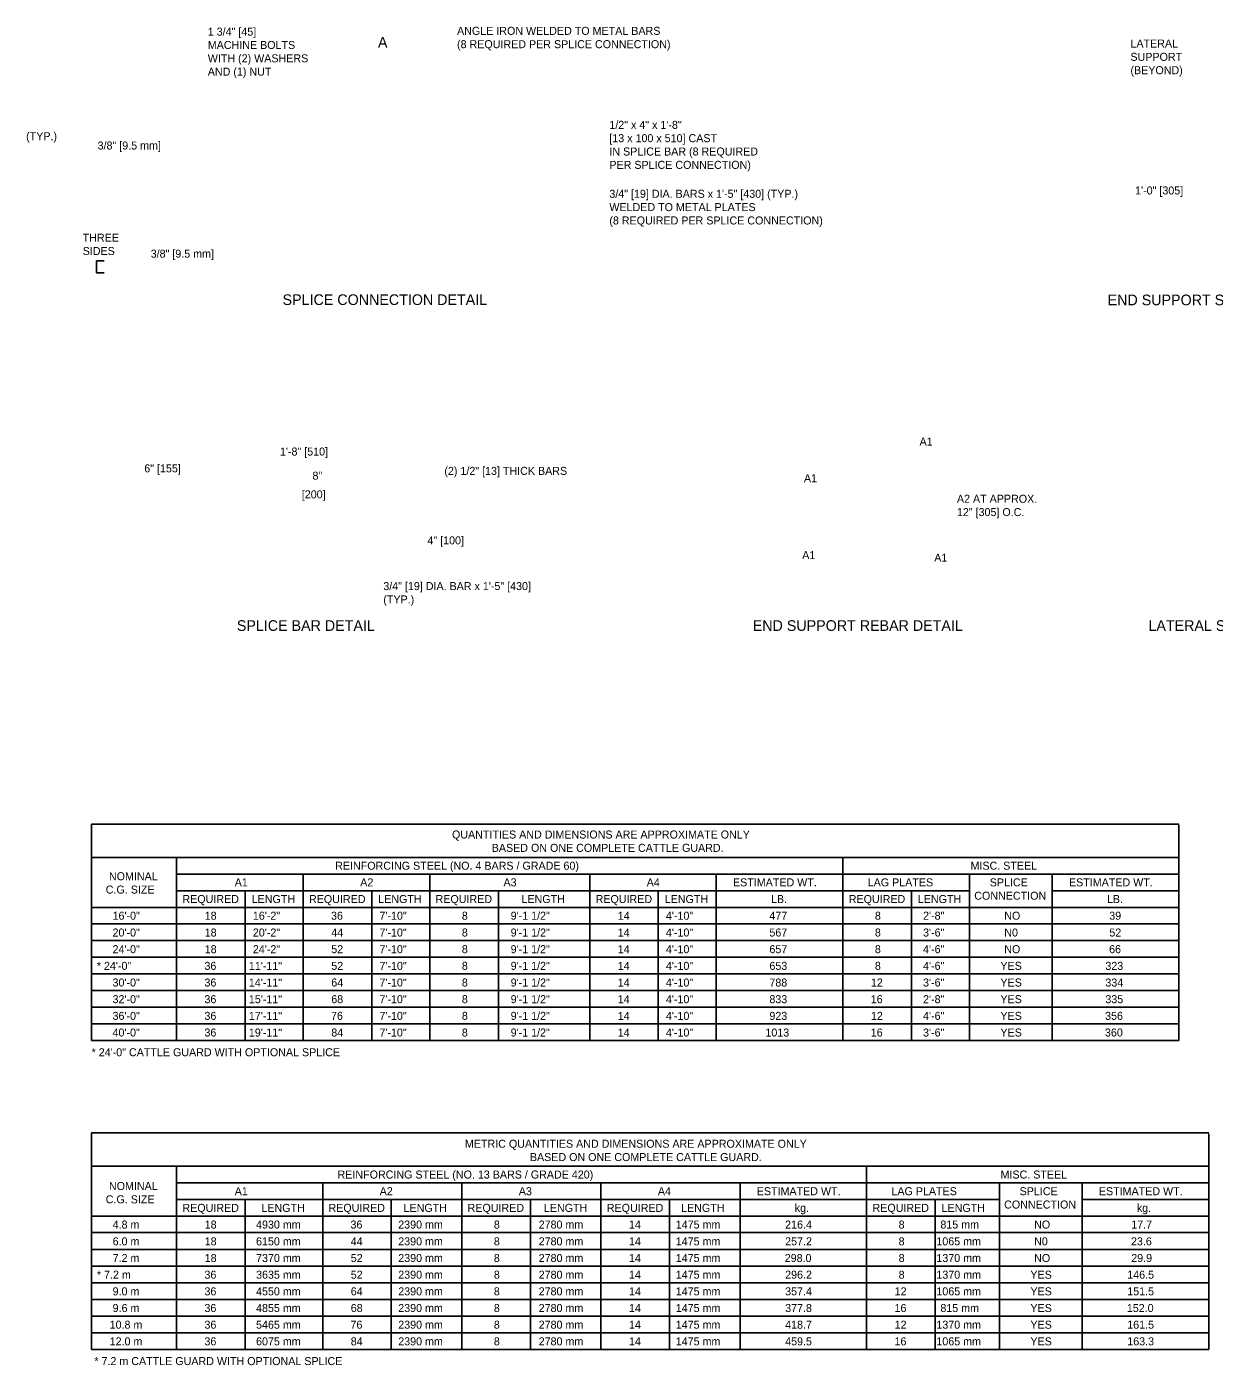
# Model space of a CAD drawing. Extents: x 49987.2 to 50044, y 49982.5 to 50011.4.
# Drawn here: x 50026.9 to 50035.8, y 49988.47 to 49998.51 of the extents above; entities that cross this region are included whole.
import ezdxf

# ---------------------------------------------------------------- set-up
doc = ezdxf.new("R2010")
doc.units = 0
doc.layers.add('Level 2', color=7, linetype='Continuous')

msp = doc.modelspace()

# ---------------------------------------------------------------- linework, layer by layer
at = {"layer": 'Level 2'}
for p, q in [((50027.476, 49996.751), (50027.418, 49996.751)), ((50027.418, 49996.751), (50027.418, 49996.661)), ((50027.476, 49996.661), (50027.418, 49996.661)), ((50027.38, 49990.903), (50027.38, 49992.526)), ((50035.534, 49992.526), (50027.38, 49992.526)), ((50035.534, 49990.903), (50035.534, 49992.521)), ((50030.578, 49992.276), (50027.38, 49992.276)), ((50028.019, 49990.903), (50028.019, 49992.276)), ((50030.578, 49992.276), (50031.816, 49992.276)), ((50031.816, 49992.276), (50033.015, 49992.276)), ((50033.015, 49992.026), (50033.015, 49992.276)), ((50033.015, 49992.276), (50035.534, 49992.276)), ((50033.015, 49992.151), (50028.019, 49992.151)), ((50028.969, 49992.026), (50028.969, 49992.151)), ((50029.918, 49992.026), (50029.918, 49992.151)), ((50031.117, 49992.026), (50031.117, 49992.151)), ((50032.066, 49992.026), (50032.066, 49992.151)), ((50033.015, 49992.151), (50035.534, 49992.151)), ((50033.964, 49990.903), (50033.964, 49992.151)), ((50034.585, 49990.903), (50034.585, 49992.151)), ((50028.019, 49992.026), (50032.066, 49992.026)), ((50028.534, 49990.903), (50028.534, 49992.026)), ((50028.969, 49990.903), (50028.969, 49992.026)), ((50029.483, 49990.903), (50029.483, 49992.026)), ((50029.918, 49990.903), (50029.918, 49992.026)), ((50030.432, 49990.903), (50030.432, 49992.026)), ((50031.117, 49990.903), (50031.117, 49992.026)), ((50031.631, 49990.903), (50031.631, 49992.026)), ((50032.066, 49990.903), (50032.066, 49992.026)), ((50032.066, 49992.026), (50033.015, 49992.026)), ((50033.015, 49990.903), (50033.015, 49992.026)), ((50033.015, 49992.026), (50033.964, 49992.026)), ((50033.53, 49990.903), (50033.53, 49992.026)), ((50033.53, 49991.028), (50033.53, 49992.026)), ((50034.585, 49990.903), (50034.585, 49992.026)), ((50034.585, 49992.026), (50035.534, 49992.026)), ((50028.019, 49991.901), (50027.38, 49991.901)), ((50028.019, 49991.901), (50028.534, 49991.901)), ((50028.534, 49991.901), (50028.969, 49991.901)), ((50028.969, 49991.901), (50035.534, 49991.901)), ((50027.38, 49991.779), (50028.019, 49991.779)), ((50028.019, 49991.779), (50028.534, 49991.779)), ((50028.534, 49991.779), (50033.53, 49991.779)), ((50033.53, 49991.779), (50035.534, 49991.779)), ((50027.38, 49991.653), (50035.534, 49991.653)), ((50027.38, 49991.528), (50035.534, 49991.528)), ((50027.38, 49991.403), (50035.534, 49991.403)), ((50027.38, 49991.278), (50035.534, 49991.278)), ((50027.38, 49991.153), (50035.534, 49991.153)), ((50027.38, 49991.028), (50035.534, 49991.028)), ((50027.38, 49990.903), (50035.534, 49990.903)), ((50027.38, 49988.587), (50027.38, 49990.21)), ((50035.758, 49990.21), (50027.38, 49990.21)), ((50035.758, 49988.587), (50035.758, 49990.204)), ((50030.818, 49989.96), (50027.38, 49989.96)), ((50028.019, 49988.587), (50028.019, 49989.96)), ((50030.818, 49989.96), (50032.244, 49989.96)), ((50032.244, 49989.96), (50033.193, 49989.96)), ((50033.193, 49989.71), (50033.193, 49989.96)), ((50033.193, 49989.96), (50035.758, 49989.96)), ((50033.193, 49989.835), (50028.019, 49989.835)), ((50029.115, 49989.71), (50029.115, 49989.835)), ((50030.158, 49989.71), (50030.158, 49989.835)), ((50031.201, 49989.71), (50031.201, 49989.835)), ((50032.244, 49989.71), (50032.244, 49989.835)), ((50033.193, 49989.835), (50035.758, 49989.835)), ((50034.188, 49988.587), (50034.188, 49989.835)), ((50034.809, 49988.587), (50034.809, 49989.835)), ((50028.019, 49989.71), (50032.244, 49989.71)), ((50028.534, 49988.587), (50028.534, 49989.71)), ((50029.115, 49988.587), (50029.115, 49989.71)), ((50029.629, 49988.587), (50029.629, 49989.71)), ((50030.158, 49988.587), (50030.158, 49989.71)), ((50030.672, 49988.587), (50030.672, 49989.71)), ((50031.201, 49988.587), (50031.201, 49989.71)), ((50031.715, 49988.587), (50031.715, 49989.71)), ((50032.244, 49988.587), (50032.244, 49989.71)), ((50032.244, 49989.71), (50033.193, 49989.71)), ((50033.193, 49988.587), (50033.193, 49989.71)), ((50033.193, 49989.71), (50034.188, 49989.71)), ((50033.708, 49988.587), (50033.708, 49989.71)), ((50034.809, 49988.587), (50034.809, 49989.71)), ((50034.809, 49989.71), (50035.758, 49989.71)), ((50028.019, 49989.585), (50027.38, 49989.585)), ((50028.019, 49989.585), (50028.534, 49989.585)), ((50028.534, 49989.585), (50029.115, 49989.585)), ((50029.115, 49989.585), (50035.758, 49989.585)), ((50027.38, 49989.463), (50028.019, 49989.463)), ((50028.019, 49989.463), (50028.534, 49989.463)), ((50028.534, 49989.463), (50033.708, 49989.463)), ((50033.708, 49989.463), (50035.758, 49989.463)), ((50027.38, 49989.337), (50035.758, 49989.337)), ((50027.38, 49989.212), (50035.758, 49989.212)), ((50027.38, 49989.087), (50035.758, 49989.087)), ((50027.38, 49988.962), (50035.758, 49988.962)), ((50027.38, 49988.837), (50035.758, 49988.837)), ((50027.38, 49988.712), (50035.758, 49988.712)), ((50027.38, 49988.587), (50035.758, 49988.587))]:
    msp.add_line(p, q, dxfattribs=at)

# ---------------------------------------------------------------- texts
for s, height, p in [('1 3/4" [45]', 0.06, (50028.253, 49998.439)), ('A', 0.08, (50029.529, 49998.349)), ('ANGLE IRON WELDED TO METAL BARS', 0.06, (50030.122, 49998.445)), ('MACHINE BOLTS', 0.06, (50028.253, 49998.339)), ('(8 REQUIRED PER SPLICE CONNECTION)', 0.06, (50030.122, 49998.345)), ('LATERAL', 0.06, (50035.171, 49998.35)), ('WITH (2) WASHERS', 0.06, (50028.253, 49998.239)), ('SUPPORT', 0.06, (50035.171, 49998.25)), ('AND (1) NUT', 0.06, (50028.253, 49998.139)), ('(BEYOND)', 0.06, (50035.171, 49998.15)), ('1/2" x 4" x 1\'-8"', 0.06, (50031.264, 49997.74)), ('(TYP.)', 0.06, (50026.891, 49997.655)), ('3/8" [9.5 mm]', 0.06, (50027.427, 49997.585)), ('[13 x 100 x 510] CAST', 0.06, (50031.264, 49997.64)), ('IN SPLICE BAR (8 REQUIRED', 0.06, (50031.264, 49997.54)), ('PER SPLICE CONNECTION)', 0.06, (50031.264, 49997.44)), ('3/4" [19] DIA. BARS x 1\'-5" [430] (TYP.)', 0.06, (50031.264, 49997.223)), ('1\'-0" [305]', 0.06, (50035.206, 49997.248)), ('WELDED TO METAL PLATES', 0.06, (50031.264, 49997.123)), ('(8 REQUIRED PER SPLICE CONNECTION)', 0.06, (50031.264, 49997.023)), ('THREE', 0.06, (50027.315, 49996.894)), ('SIDES', 0.06, (50027.315, 49996.794)), ('3/8" [9.5 mm]', 0.06, (50027.825, 49996.774)), ('SPLICE CONNECTION DETAIL', 0.08, (50028.814, 49996.419)), ('END SUPPORT SECTION A-A', 0.08, (50035, 49996.417)), ('A1', 0.06, (50033.59, 49995.365)), ('1\'-8" [510]', 0.06, (50028.794, 49995.29)), ('6" [155]', 0.06, (50027.777, 49995.164)), ('8"', 0.06, (50029.038, 49995.109)), ('(2) 1/2" [13] THICK BARS', 0.06, (50030.027, 49995.145)), ('A1', 0.06, (50032.723, 49995.09)), ('[200]', 0.06, (50028.958, 49994.969)), ('A2 AT APPROX. ', 0.06, (50033.87, 49994.936)), ('12" [305] O.C.', 0.06, (50033.87, 49994.836)), ('4" [100]', 0.06, (50029.9, 49994.624)), ('A1', 0.06, (50032.71, 49994.513)), ('A1', 0.06, (50033.7, 49994.494)), ('3/4" [19] DIA. BAR x 1\'-5" [430]', 0.06, (50029.569, 49994.281)), ('(TYP.)', 0.06, (50029.569, 49994.181)), ('SPLICE BAR DETAIL', 0.08, (50028.471, 49993.975)), ('END SUPPORT REBAR DETAIL', 0.08, (50032.339, 49993.975)), ('LATERAL SUPPORT REBAR DETAIL', 0.08, (50035.306, 49993.975)), ('QUANTITIES AND DIMENSIONS ARE APPROXIMATE ONLY', 0.06, (50030.084, 49992.418)), ('BASED ON ONE COMPLETE CATTLE GUARD.', 0.06, (50030.382, 49992.318)), ('REINFORCING STEEL (NO. 4 BARS / GRADE 60)', 0.06, (50029.208, 49992.184)), ('MISC. STEEL', 0.06, (50033.972, 49992.184)), ('NOMINAL', 0.06, (50027.512, 49992.105)), ('A1', 0.06, (50028.455, 49992.059)), ('A2', 0.06, (50029.396, 49992.059)), ('A3', 0.06, (50030.47, 49992.059)), ('A4', 0.06, (50031.544, 49992.059)), ('ESTIMATED WT.', 0.06, (50032.191, 49992.059)), ('LAG PLATES', 0.06, (50033.201, 49992.059)), ('SPLICE', 0.06, (50034.116, 49992.059)), ('ESTIMATED WT.', 0.06, (50034.71, 49992.059)), ('C.G. SIZE', 0.06, (50027.488, 49992.005)), ('CONNECTION', 0.06, (50034, 49991.959)), ('REQUIRED', 0.06, (50028.063, 49991.934)), ('LENGTH', 0.06, (50028.582, 49991.934)), ('REQUIRED', 0.06, (50029.012, 49991.934)), ('LENGTH', 0.06, (50029.531, 49991.934)), ('REQUIRED', 0.06, (50029.961, 49991.934)), ('LENGTH', 0.06, (50030.605, 49991.934)), ('REQUIRED', 0.06, (50031.161, 49991.934)), ('LENGTH', 0.06, (50031.679, 49991.934)), ('LB.', 0.06, (50032.476, 49991.934)), ('REQUIRED', 0.06, (50033.059, 49991.934)), ('LENGTH', 0.06, (50033.577, 49991.934)), ('LB.', 0.06, (50034.995, 49991.934)), ('16\'-0"', 0.06, (50027.539, 49991.809)), ('18', 0.06, (50028.23, 49991.809)), ('16\'-2"', 0.06, (50028.591, 49991.809)), ('36', 0.06, (50029.177, 49991.809)), ('7\'-10"', 0.06, (50029.54, 49991.809)), ('8', 0.06, (50030.158, 49991.809)), ('9\'-1 1/2"', 0.06, (50030.524, 49991.809)), ('14', 0.06, (50031.327, 49991.809)), ('4\'-10"', 0.06, (50031.688, 49991.809)), ('477', 0.06, (50032.464, 49991.809)), ('8', 0.06, (50033.255, 49991.809)), ('2\'-8"', 0.06, (50033.616, 49991.809)), ('NO', 0.06, (50034.225, 49991.809)), ('39', 0.06, (50035.012, 49991.809)), ('20\'-0"', 0.06, (50027.539, 49991.683)), ('18', 0.06, (50028.23, 49991.683)), ('20\'-2"', 0.06, (50028.591, 49991.683)), ('44', 0.06, (50029.179, 49991.683)), ('7\'-10"', 0.06, (50029.54, 49991.683)), ('8', 0.06, (50030.158, 49991.683)), ('9\'-1 1/2"', 0.06, (50030.524, 49991.683)), ('14', 0.06, (50031.327, 49991.683)), ('4\'-10"', 0.06, (50031.688, 49991.683)), ('567', 0.06, (50032.464, 49991.683)), ('8', 0.06, (50033.255, 49991.683)), ('3\'-6"', 0.06, (50033.616, 49991.683)), ('N0', 0.06, (50034.225, 49991.683)), ('52', 0.06, (50035.013, 49991.683)), ('24\'-0"', 0.06, (50027.539, 49991.558)), ('18', 0.06, (50028.23, 49991.558)), ('24\'-2"', 0.06, (50028.591, 49991.558)), ('52', 0.06, (50029.179, 49991.558)), ('7\'-10"', 0.06, (50029.54, 49991.558)), ('8', 0.06, (50030.158, 49991.558)), ('9\'-1 1/2"', 0.06, (50030.524, 49991.558)), ('14', 0.06, (50031.327, 49991.558)), ('4\'-10"', 0.06, (50031.688, 49991.558)), ('657', 0.06, (50032.464, 49991.558)), ('8', 0.06, (50033.255, 49991.558)), ('4\'-6"', 0.06, (50033.616, 49991.558)), ('NO', 0.06, (50034.225, 49991.558)), ('66', 0.06, (50035.011, 49991.558)), ('9\'-1 1/2"', 0.06, (50030.524, 49991.433)), ('* 24\'-0"', 0.06, (50027.421, 49991.433)), ('36', 0.06, (50028.228, 49991.433)), ('11\'-11"', 0.06, (50028.561, 49991.433)), ('52', 0.06, (50029.179, 49991.433)), ('7\'-10"', 0.06, (50029.54, 49991.433)), ('8', 0.06, (50030.158, 49991.433)), ('14', 0.06, (50031.327, 49991.433)), ('4\'-10"', 0.06, (50031.688, 49991.433)), ('653', 0.06, (50032.464, 49991.433)), ('8', 0.06, (50033.255, 49991.433)), ('4\'-6"', 0.06, (50033.616, 49991.433)), ('YES', 0.06, (50034.196, 49991.433)), ('323', 0.06, (50034.983, 49991.433)), ('30\'-0"', 0.06, (50027.539, 49991.308)), ('36', 0.06, (50028.228, 49991.308)), ('14\'-11"', 0.06, (50028.561, 49991.308)), ('64', 0.06, (50029.179, 49991.308)), ('7\'-10"', 0.06, (50029.54, 49991.308)), ('8', 0.06, (50030.158, 49991.308)), ('9\'-1 1/2"', 0.06, (50030.524, 49991.308)), ('14', 0.06, (50031.327, 49991.308)), ('4\'-10"', 0.06, (50031.688, 49991.308)), ('788', 0.06, (50032.464, 49991.308)), ('12', 0.06, (50033.225, 49991.308)), ('3\'-6"', 0.06, (50033.616, 49991.308)), ('YES', 0.06, (50034.196, 49991.308)), ('334', 0.06, (50034.983, 49991.308)), ('32\'-0"', 0.06, (50027.539, 49991.183)), ('36', 0.06, (50028.228, 49991.183)), ('15\'-11"', 0.06, (50028.561, 49991.183)), ('68', 0.06, (50029.179, 49991.183)), ('7\'-10"', 0.06, (50029.54, 49991.183)), ('8', 0.06, (50030.158, 49991.183)), ('9\'-1 1/2"', 0.06, (50030.524, 49991.183)), ('14', 0.06, (50031.327, 49991.183)), ('4\'-10"', 0.06, (50031.688, 49991.183)), ('833', 0.06, (50032.464, 49991.183)), ('16', 0.06, (50033.224, 49991.183)), ('2\'-8"', 0.06, (50033.616, 49991.183)), ('YES', 0.06, (50034.196, 49991.183)), ('335', 0.06, (50034.983, 49991.183)), ('36\'-0"', 0.06, (50027.539, 49991.058)), ('36', 0.06, (50028.228, 49991.058)), ('17\'-11"', 0.06, (50028.561, 49991.058)), ('76', 0.06, (50029.177, 49991.058)), ('7\'-10"', 0.06, (50029.54, 49991.058)), ('8', 0.06, (50030.158, 49991.058)), ('9\'-1 1/2"', 0.06, (50030.524, 49991.058)), ('14', 0.06, (50031.327, 49991.058)), ('4\'-10"', 0.06, (50031.688, 49991.058)), ('923', 0.06, (50032.464, 49991.058)), ('12', 0.06, (50033.225, 49991.058)), ('4\'-6"', 0.06, (50033.616, 49991.058)), ('YES', 0.06, (50034.196, 49991.058)), ('356', 0.06, (50034.981, 49991.058)), ('9\'-1 1/2"', 0.06, (50030.524, 49990.933)), ('40\'-0"', 0.06, (50027.539, 49990.933)), ('36', 0.06, (50028.228, 49990.933)), ('19\'-11"', 0.06, (50028.561, 49990.933)), ('84', 0.06, (50029.179, 49990.933)), ('7\'-10"', 0.06, (50029.54, 49990.933)), ('8', 0.06, (50030.158, 49990.933)), ('14', 0.06, (50031.327, 49990.933)), ('4\'-10"', 0.06, (50031.688, 49990.933)), ('1013', 0.06, (50032.434, 49990.933)), ('16', 0.06, (50033.224, 49990.933)), ('3\'-6"', 0.06, (50033.616, 49990.933)), ('YES', 0.06, (50034.196, 49990.933)), ('360', 0.06, (50034.98, 49990.933)), ('* 24\'-0" CATTLE GUARD WITH OPTIONAL SPLICE', 0.06, (50027.382, 49990.785)), ('METRIC QUANTITIES AND DIMENSIONS ARE APPROXIMATE ONLY', 0.06, (50030.181, 49990.099)), ('BASED ON ONE COMPLETE CATTLE GUARD.', 0.06, (50030.668, 49989.999)), ('REINFORCING STEEL (NO. 13 BARS / GRADE 420)', 0.06, (50029.226, 49989.868)), ('MISC. STEEL', 0.06, (50034.197, 49989.868)), ('NOMINAL', 0.06, (50027.512, 49989.782)), ('A1', 0.06, (50028.455, 49989.743)), ('A2', 0.06, (50029.542, 49989.743)), ('A3', 0.06, (50030.585, 49989.743)), ('A4', 0.06, (50031.628, 49989.743)), ('ESTIMATED WT.', 0.06, (50032.369, 49989.743)), ('LAG PLATES', 0.06, (50033.379, 49989.743)), ('SPLICE', 0.06, (50034.34, 49989.743)), ('ESTIMATED WT.', 0.06, (50034.934, 49989.743)), ('C.G. SIZE', 0.06, (50027.488, 49989.682)), ('CONNECTION', 0.06, (50034.224, 49989.643)), ('REQUIRED', 0.06, (50028.063, 49989.618)), ('LENGTH', 0.06, (50028.655, 49989.618)), ('REQUIRED', 0.06, (50029.158, 49989.618)), ('LENGTH', 0.06, (50029.721, 49989.618)), ('REQUIRED', 0.06, (50030.201, 49989.618)), ('LENGTH', 0.06, (50030.773, 49989.618)), ('REQUIRED', 0.06, (50031.245, 49989.618)), ('LENGTH', 0.06, (50031.802, 49989.618)), ('kg.', 0.06, (50032.654, 49989.618)), ('REQUIRED', 0.06, (50033.237, 49989.618)), ('LENGTH', 0.06, (50033.755, 49989.618)), ('kg.', 0.06, (50035.219, 49989.618)), ('  4.8 m', 0.06, (50027.495, 49989.493)), ('18', 0.06, (50028.23, 49989.493)), ('4930 mm', 0.06, (50028.615, 49989.493)), ('36', 0.06, (50029.323, 49989.493)), ('2390 mm', 0.06, (50029.681, 49989.493)), ('8', 0.06, (50030.398, 49989.493)), ('2780 mm', 0.06, (50030.734, 49989.493)), ('14', 0.06, (50031.411, 49989.493)), ('1475 mm', 0.06, (50031.762, 49989.493)), ('216.4', 0.06, (50032.582, 49989.493)), ('8', 0.06, (50033.433, 49989.493)), ('815 mm', 0.06, (50033.746, 49989.493)), ('NO', 0.06, (50034.449, 49989.493)), ('17.7', 0.06, (50035.177, 49989.493)), ('  6.0 m', 0.06, (50027.495, 49989.367)), ('18', 0.06, (50028.23, 49989.367)), ('6150 mm', 0.06, (50028.615, 49989.367)), ('44', 0.06, (50029.325, 49989.367)), ('2390 mm', 0.06, (50029.681, 49989.367)), ('8', 0.06, (50030.398, 49989.367)), ('2780 mm', 0.06, (50030.734, 49989.367)), ('14', 0.06, (50031.411, 49989.367)), ('1475 mm', 0.06, (50031.762, 49989.367)), ('257.2', 0.06, (50032.582, 49989.367)), ('8', 0.06, (50033.433, 49989.367)), ('1065 mm', 0.06, (50033.716, 49989.367)), ('N0', 0.06, (50034.449, 49989.367)), ('23.6', 0.06, (50035.175, 49989.367)), ('  7.2 m', 0.06, (50027.495, 49989.242)), ('18', 0.06, (50028.23, 49989.242)), ('7370 mm', 0.06, (50028.615, 49989.242)), ('52', 0.06, (50029.325, 49989.242)), ('2390 mm', 0.06, (50029.681, 49989.242)), ('8', 0.06, (50030.398, 49989.242)), ('2780 mm', 0.06, (50030.734, 49989.242)), ('14', 0.06, (50031.411, 49989.242)), ('1475 mm', 0.06, (50031.762, 49989.242)), ('298.0', 0.06, (50032.579, 49989.242)), ('8', 0.06, (50033.433, 49989.242)), ('1370 mm', 0.06, (50033.716, 49989.242)), ('NO', 0.06, (50034.449, 49989.242)), ('29.9', 0.06, (50035.177, 49989.242)), ('  * 7.2 m', 0.06, (50027.377, 49989.117)), ('36', 0.06, (50028.228, 49989.117)), ('3635 mm', 0.06, (50028.615, 49989.117)), ('52', 0.06, (50029.325, 49989.117)), ('2390 mm', 0.06, (50029.681, 49989.117)), ('8', 0.06, (50030.398, 49989.117)), ('2780 mm', 0.06, (50030.734, 49989.117)), ('14', 0.06, (50031.411, 49989.117)), ('1475 mm', 0.06, (50031.762, 49989.117)), ('296.2', 0.06, (50032.582, 49989.117)), ('8', 0.06, (50033.433, 49989.117)), ('1370 mm', 0.06, (50033.716, 49989.117)), ('YES', 0.06, (50034.421, 49989.117)), ('146.5', 0.06, (50035.147, 49989.117)), ('  9.0 m', 0.06, (50027.495, 49988.992)), ('36', 0.06, (50028.228, 49988.992)), ('4550 mm', 0.06, (50028.615, 49988.992)), ('64', 0.06, (50029.325, 49988.992)), ('2390 mm', 0.06, (50029.681, 49988.992)), ('8', 0.06, (50030.398, 49988.992)), ('2780 mm', 0.06, (50030.734, 49988.992)), ('14', 0.06, (50031.411, 49988.992)), ('1475 mm', 0.06, (50031.762, 49988.992)), ('357.4', 0.06, (50032.582, 49988.992)), ('12', 0.06, (50033.403, 49988.992)), ('1065 mm', 0.06, (50033.716, 49988.992)), ('YES', 0.06, (50034.421, 49988.992)), ('151.5', 0.06, (50035.147, 49988.992)), ('  9.6 m', 0.06, (50027.495, 49988.867)), ('36', 0.06, (50028.228, 49988.867)), ('4855 mm', 0.06, (50028.615, 49988.867)), ('68', 0.06, (50029.325, 49988.867)), ('2390 mm', 0.06, (50029.681, 49988.867)), ('8', 0.06, (50030.398, 49988.867)), ('2780 mm', 0.06, (50030.734, 49988.867)), ('14', 0.06, (50031.411, 49988.867)), ('1475 mm', 0.06, (50031.762, 49988.867)), ('377.8', 0.06, (50032.582, 49988.867)), ('16', 0.06, (50033.402, 49988.867)), ('815 mm', 0.06, (50033.746, 49988.867)), ('YES', 0.06, (50034.421, 49988.867)), ('152.0', 0.06, (50035.144, 49988.867)), (' 10.8 m', 0.06, (50027.495, 49988.742)), ('36', 0.06, (50028.228, 49988.742)), ('5465 mm', 0.06, (50028.615, 49988.742)), ('76', 0.06, (50029.323, 49988.742)), ('2390 mm', 0.06, (50029.681, 49988.742)), ('8', 0.06, (50030.398, 49988.742)), ('2780 mm', 0.06, (50030.734, 49988.742)), ('14', 0.06, (50031.411, 49988.742)), ('1475 mm', 0.06, (50031.762, 49988.742)), ('418.7', 0.06, (50032.582, 49988.742)), ('12', 0.06, (50033.403, 49988.742)), ('1370 mm', 0.06, (50033.716, 49988.742)), ('YES', 0.06, (50034.421, 49988.742)), ('161.5', 0.06, (50035.147, 49988.742)), (' 12.0 m', 0.06, (50027.495, 49988.617)), ('36', 0.06, (50028.228, 49988.617)), ('6075 mm', 0.06, (50028.615, 49988.617)), ('84', 0.06, (50029.325, 49988.617)), ('2390 mm', 0.06, (50029.681, 49988.617)), ('8', 0.06, (50030.398, 49988.617)), ('2780 mm', 0.06, (50030.734, 49988.617)), ('14', 0.06, (50031.411, 49988.617)), ('1475 mm', 0.06, (50031.762, 49988.617)), ('459.5', 0.06, (50032.582, 49988.617)), ('16', 0.06, (50033.402, 49988.617)), ('1065 mm', 0.06, (50033.716, 49988.617)), ('YES', 0.06, (50034.421, 49988.617)), ('163.3', 0.06, (50035.147, 49988.617)), ('* 7.2 m CATTLE GUARD WITH OPTIONAL SPLICE', 0.06, (50027.403, 49988.469))]:
    msp.add_text(s, height=height, dxfattribs=at).set_placement(p)

doc.saveas('drawing.dxf')
